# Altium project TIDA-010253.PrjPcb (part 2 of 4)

## Sheet MCU_DockHearder_V3.SchDoc
size A2; Date: Not shown in title block; ApprovedBy: Not shown in title block; CheckedBy: Not shown in title block; Author: Not shown in title block; CompanyName: Not shown in title block; Engineer: Not shown in title block; Organization: Not shown in title block; Address1: Not shown in title block; Address2: Not shown in title block; Address3: Not shown in title block; Address4: Not shown in title block; DocumentNumber: 1; Revision: Use project parameter SCH_Rev; SheetNumber: 6; SheetTotal: 7; PageSetup: Record=PageOptions¦CenterHorizontal=True¦CenterVertical=True¦PrintScale=0.69¦XCorrection=1.00¦YCorrection=1.00¦PrintKind=0¦BorderSize=5000000¦LeftOffset=0¦BottomOffset=0¦Orientation=2¦PaperLength=1000¦PaperWidth=1000¦Scale=100¦PaperSource=15¦PrintQuality=600¦MediaType=1¦DitherType=10¦PaperKind=Letter¦PrintScaleMode=1
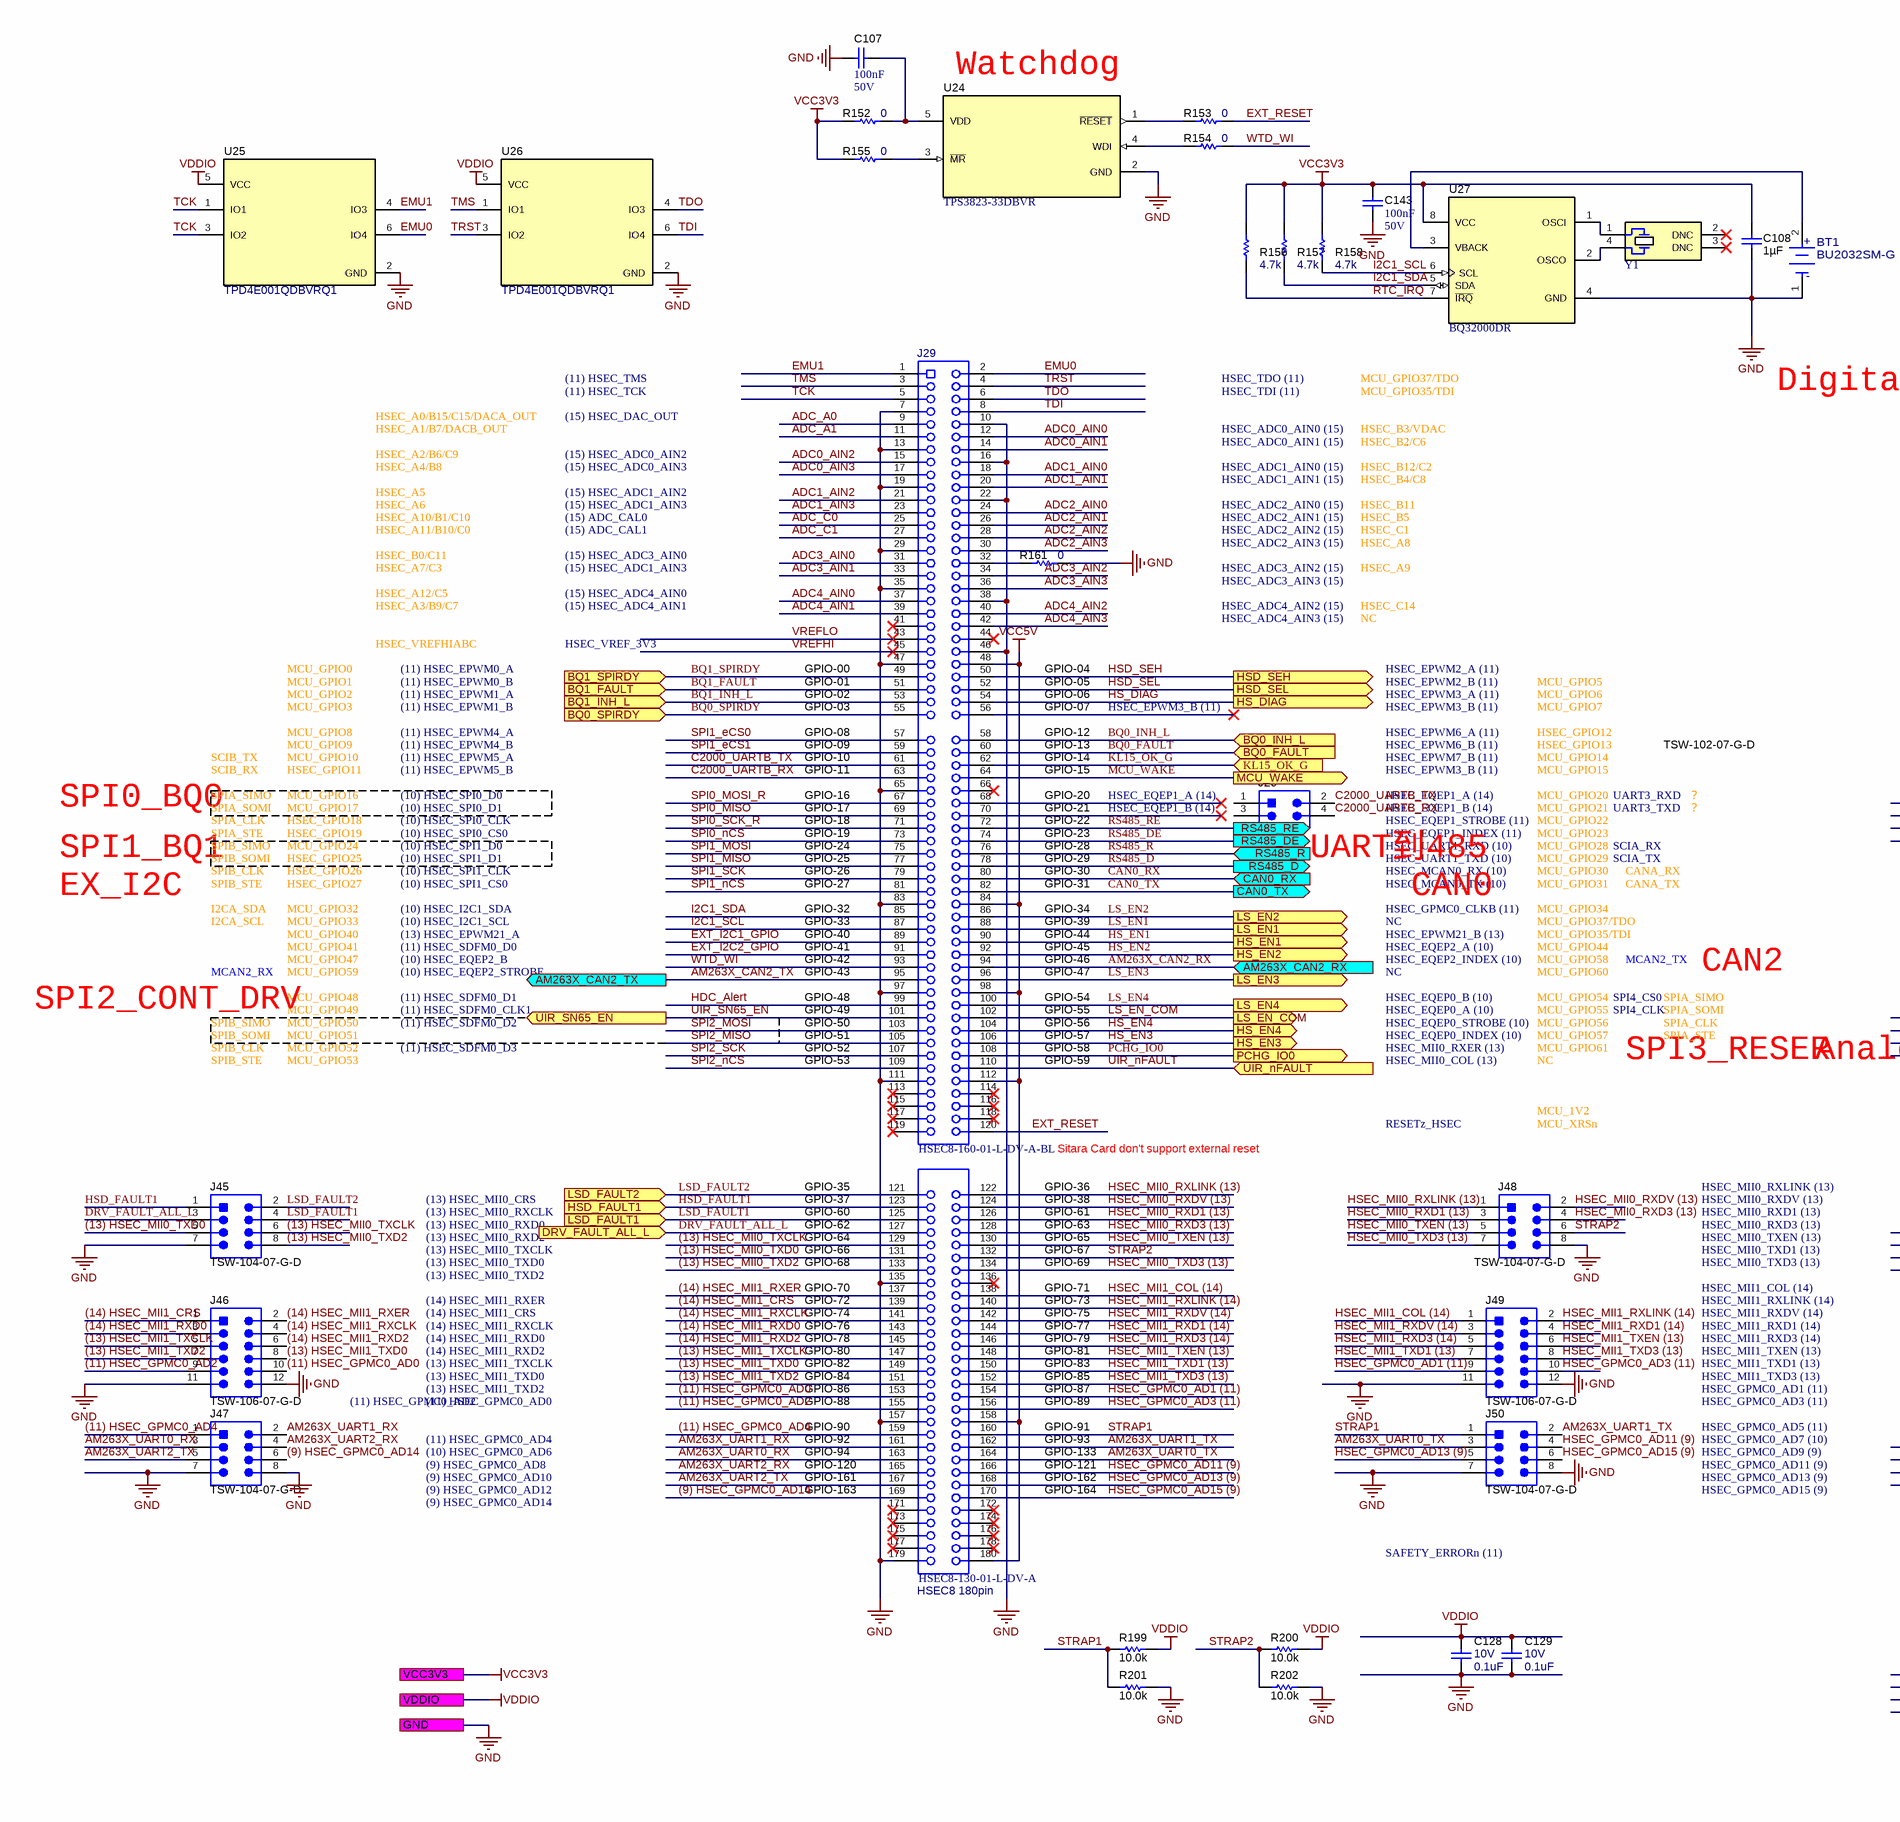
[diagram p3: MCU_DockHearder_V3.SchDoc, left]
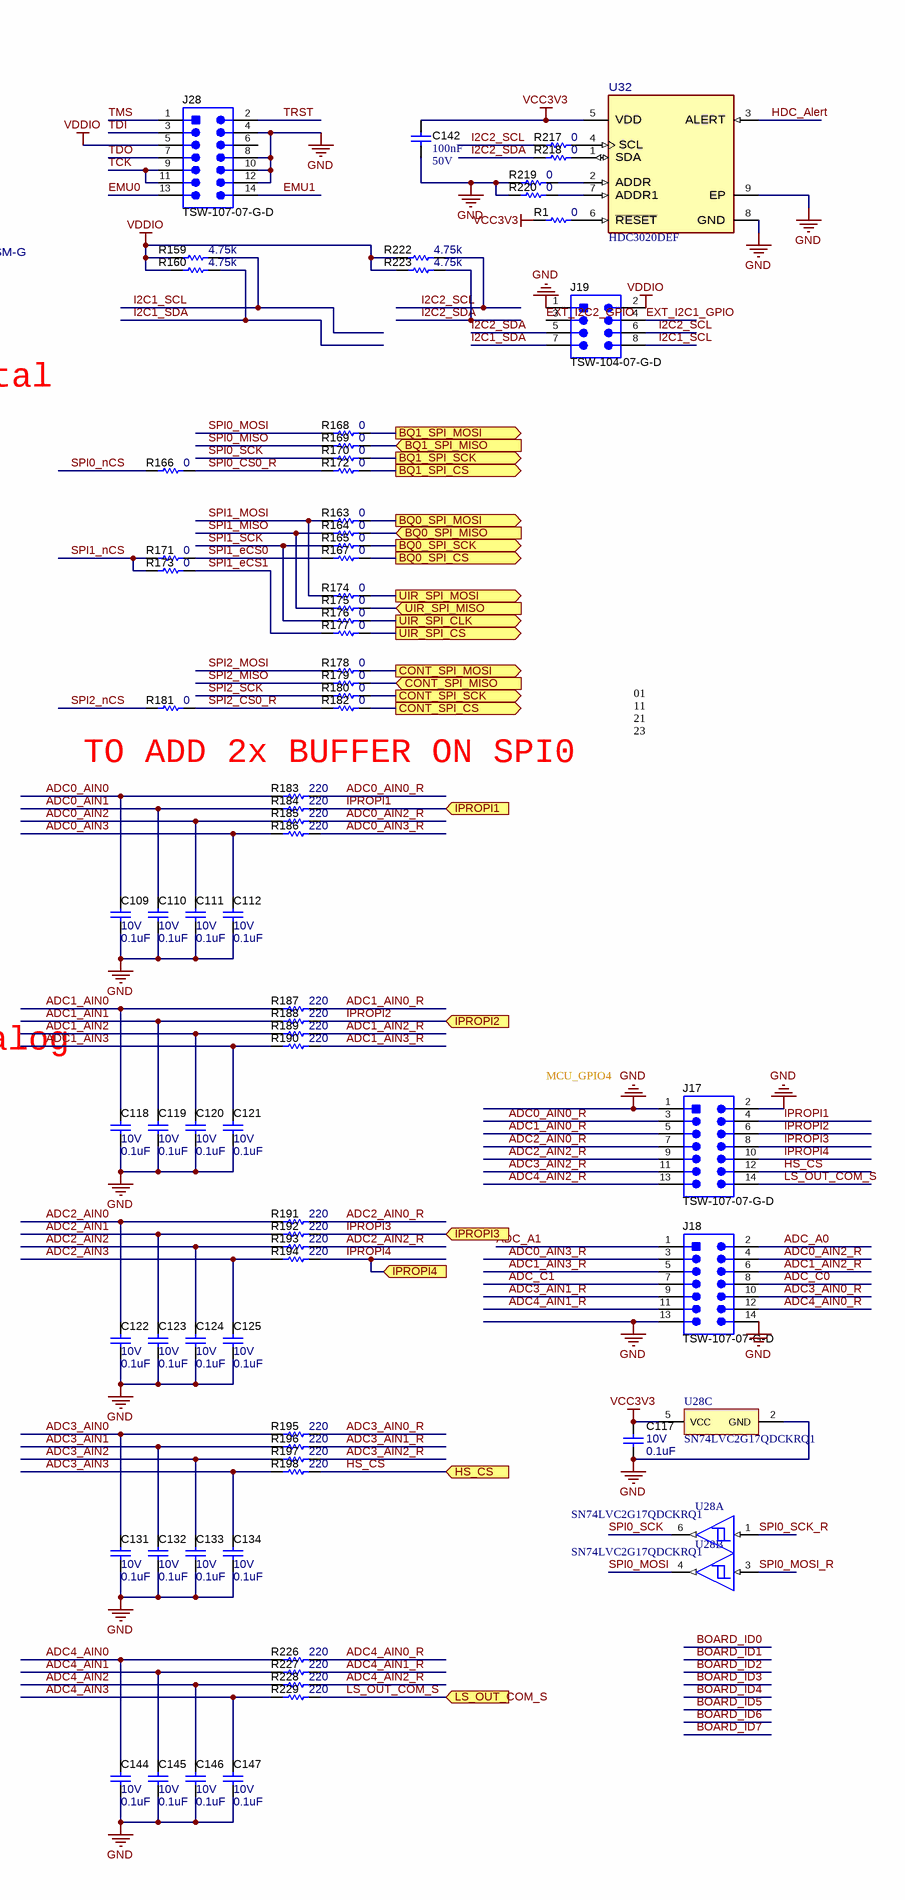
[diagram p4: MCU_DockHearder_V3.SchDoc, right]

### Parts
BT1  BU2032SM-G  [FP-BU2032SM-G_SMT2-MFG]
C107  Cap_F: 100nF  VDC_V: 50V  [0805_HV]  (hidden comment: 08055C104JAT2A)
C108  Cap_F: 1µF  [0603L]  (hidden comment: CGA3E1X7R1E105K080AD)
C109  VDC_V: 10V  ValueDisplayed: 0.1uF  [0402]  (hidden comment: GCM155R71A104KA55D)
C110  VDC_V: 10V  ValueDisplayed: 0.1uF  [0402]  (hidden comment: GCM155R71A104KA55D)
C111  VDC_V: 10V  ValueDisplayed: 0.1uF  [0402]  (hidden comment: GCM155R71A104KA55D)
C112  VDC_V: 10V  ValueDisplayed: 0.1uF  [0402]  (hidden comment: GCM155R71A104KA55D)
C117  VDC_V: 10V  ValueDisplayed: 0.1uF  [0402]  (hidden comment: GCM155R71A104KA55D)
C118  VDC_V: 10V  ValueDisplayed: 0.1uF  [0402]  (hidden comment: GCM155R71A104KA55D)
C119  VDC_V: 10V  ValueDisplayed: 0.1uF  [0402]  (hidden comment: GCM155R71A104KA55D)
C120  VDC_V: 10V  ValueDisplayed: 0.1uF  [0402]  (hidden comment: GCM155R71A104KA55D)
C121  VDC_V: 10V  ValueDisplayed: 0.1uF  [0402]  (hidden comment: GCM155R71A104KA55D)
C122  VDC_V: 10V  ValueDisplayed: 0.1uF  [0402]  (hidden comment: GCM155R71A104KA55D)
C123  VDC_V: 10V  ValueDisplayed: 0.1uF  [0402]  (hidden comment: GCM155R71A104KA55D)
C124  VDC_V: 10V  ValueDisplayed: 0.1uF  [0402]  (hidden comment: GCM155R71A104KA55D)
C125  VDC_V: 10V  ValueDisplayed: 0.1uF  [0402]  (hidden comment: GCM155R71A104KA55D)
C128  VDC_V: 10V  ValueDisplayed: 0.1uF  [0402]  (hidden comment: GCM155R71A104KA55D)
C129  VDC_V: 10V  ValueDisplayed: 0.1uF  [0402]  (hidden comment: GCM155R71A104KA55D)
C131  VDC_V: 10V  ValueDisplayed: 0.1uF  [0402]  (hidden comment: GCM155R71A104KA55D)
C132  VDC_V: 10V  ValueDisplayed: 0.1uF  [0402]  (hidden comment: GCM155R71A104KA55D)
C133  VDC_V: 10V  ValueDisplayed: 0.1uF  [0402]  (hidden comment: GCM155R71A104KA55D)
C134  VDC_V: 10V  ValueDisplayed: 0.1uF  [0402]  (hidden comment: GCM155R71A104KA55D)
C142  Cap_F: 100nF  VDC_V: 50V  [0805_HV]  (hidden comment: 08055C104JAT2A)
C143  Cap_F: 100nF  VDC_V: 50V  [0805_HV]  (hidden comment: 08055C104JAT2A)
C144  VDC_V: 10V  ValueDisplayed: 0.1uF  [0402]  (hidden comment: GCM155R71A104KA55D)
C145  VDC_V: 10V  ValueDisplayed: 0.1uF  [0402]  (hidden comment: GCM155R71A104KA55D)
C146  VDC_V: 10V  ValueDisplayed: 0.1uF  [0402]  (hidden comment: GCM155R71A104KA55D)
C147  VDC_V: 10V  ValueDisplayed: 0.1uF  [0402]  (hidden comment: GCM155R71A104KA55D)
J17  TSW-107-07-G-D  [TSW-107-07-X-D]
J18  TSW-107-07-G-D  [TSW-107-07-X-D]
J19  TSW-104-07-G-D  [TSW-104-07-G-D]
J20  TSW-102-07-G-D  [TSW-102-07-G-D]
J28  TSW-107-07-G-D  [TSW-107-07-X-D]
J29  HSEC8 180pin  [HEADER_HSEC8_180_DV]
J45  TSW-104-07-G-D  [TSW-104-07-G-D]
J46  TSW-106-07-G-D  [TSW-106-07-G-D]
J47  TSW-104-07-G-D  [TSW-104-07-G-D]
J48  TSW-104-07-G-D  [TSW-104-07-G-D]
J49  TSW-106-07-G-D  [TSW-106-07-G-D]
J50  TSW-104-07-G-D  [TSW-104-07-G-D]
R1  ValueDisplayed: 0  [0402]  (hidden comment: RK73Z1ETTP)
R152  ValueDisplayed: 0  [0402]  (hidden comment: CRCW04020000Z0ED)
R153  ValueDisplayed: 0  [0402]  (hidden comment: CRCW04020000Z0ED)
R154  ValueDisplayed: 0  [0402]  (hidden comment: CRCW04020000Z0ED)
R155  ValueDisplayed: 0  [0402]  (hidden comment: CRCW04020000Z0ED)
R156  ValueDisplayed: 4.7k  [0402]  (hidden comment: CRCW04024K70JNED)
R157  ValueDisplayed: 4.7k  [0402]  (hidden comment: CRCW04024K70JNED)
R158  ValueDisplayed: 4.7k  [0402]  (hidden comment: CRCW04024K70JNED)
R159  ValueDisplayed: 4.75k  [0402]  (hidden comment: CRCW04024K75FKED)
R160  ValueDisplayed: 4.75k  [0402]  (hidden comment: CRCW04024K75FKED)
R161  ValueDisplayed: 0  [0402]  (hidden comment: RK73Z1ETTP)
R163  ValueDisplayed: 0  [0402]  (hidden comment: CRCW04020000Z0ED)
R164  ValueDisplayed: 0  [0402]  (hidden comment: CRCW04020000Z0ED)
R165  ValueDisplayed: 0  [0402]  (hidden comment: CRCW04020000Z0ED)
R166  ValueDisplayed: 0  [0402]  (hidden comment: CRCW04020000Z0ED)
R167  ValueDisplayed: 0  [0402]  (hidden comment: CRCW04020000Z0ED)
R168  ValueDisplayed: 0  [0402]  (hidden comment: CRCW04020000Z0ED)
R169  ValueDisplayed: 0  [0402]  (hidden comment: CRCW04020000Z0ED)
R170  ValueDisplayed: 0  [0402]  (hidden comment: CRCW04020000Z0ED)
R171  ValueDisplayed: 0  [0402]  (hidden comment: CRCW04020000Z0ED)
R172  ValueDisplayed: 0  [0402]  (hidden comment: CRCW04020000Z0ED)
R173  ValueDisplayed: 0  [0402]  (hidden comment: CRCW04020000Z0ED)
R174  ValueDisplayed: 0  [0402]  (hidden comment: CRCW04020000Z0ED)
R175  ValueDisplayed: 0  [0402]  (hidden comment: CRCW04020000Z0ED)
R176  ValueDisplayed: 0  [0402]  (hidden comment: CRCW04020000Z0ED)
R177  ValueDisplayed: 0  [0402]  (hidden comment: CRCW04020000Z0ED)
R178  ValueDisplayed: 0  [0402]  (hidden comment: CRCW04020000Z0ED)
R179  ValueDisplayed: 0  [0402]  (hidden comment: CRCW04020000Z0ED)
R180  ValueDisplayed: 0  [0402]  (hidden comment: CRCW04020000Z0ED)
R181  ValueDisplayed: 0  [0402]  (hidden comment: CRCW04020000Z0ED)
R182  ValueDisplayed: 0  [0402]  (hidden comment: CRCW04020000Z0ED)
R183  ValueDisplayed: 220  [0402]  (hidden comment: CRCW0402220RJNED)
R184  ValueDisplayed: 220  [0402]  (hidden comment: CRCW0402220RJNED)
R185  ValueDisplayed: 220  [0402]  (hidden comment: CRCW0402220RJNED)
R186  ValueDisplayed: 220  [0402]  (hidden comment: CRCW0402220RJNED)
R187  ValueDisplayed: 220  [0402]  (hidden comment: CRCW0402220RJNED)
R188  ValueDisplayed: 220  [0402]  (hidden comment: CRCW0402220RJNED)
R189  ValueDisplayed: 220  [0402]  (hidden comment: CRCW0402220RJNED)
R190  ValueDisplayed: 220  [0402]  (hidden comment: CRCW0402220RJNED)
R191  ValueDisplayed: 220  [0402]  (hidden comment: CRCW0402220RJNED)
R192  ValueDisplayed: 220  [0402]  (hidden comment: CRCW0402220RJNED)
R193  ValueDisplayed: 220  [0402]  (hidden comment: CRCW0402220RJNED)
R194  ValueDisplayed: 220  [0402]  (hidden comment: CRCW0402220RJNED)
R195  ValueDisplayed: 220  [0402]  (hidden comment: CRCW0402220RJNED)
R196  ValueDisplayed: 220  [0402]  (hidden comment: CRCW0402220RJNED)
R197  ValueDisplayed: 220  [0402]  (hidden comment: CRCW0402220RJNED)
R198  ValueDisplayed: 220  [0402]  (hidden comment: CRCW0402220RJNED)
R199  ValueDisplayed: 10.0k  [0402]  (hidden comment: RC0402FR-0710KL)
R200  ValueDisplayed: 10.0k  [0402]  (hidden comment: RC0402FR-0710KL)
R201  ValueDisplayed: 10.0k  [0402]  (hidden comment: RC0402FR-0710KL)
R202  ValueDisplayed: 10.0k  [0402]  (hidden comment: RC0402FR-0710KL)
R217  ValueDisplayed: 0  [0402]  (hidden comment: RK73Z1ETTP)
R218  ValueDisplayed: 0  [0402]  (hidden comment: RK73Z1ETTP)
R219  ValueDisplayed: 0  [0402]  (hidden comment: RK73Z1ETTP)
R220  ValueDisplayed: 0  [0402]  (hidden comment: RK73Z1ETTP)
R222  ValueDisplayed: 4.75k  [0402]  (hidden comment: CRCW04024K75FKED)
R223  ValueDisplayed: 4.75k  [0402]  (hidden comment: CRCW04024K75FKED)
R226  ValueDisplayed: 220  [0402]  (hidden comment: CRCW0402220RJNED)
R227  ValueDisplayed: 220  [0402]  (hidden comment: CRCW0402220RJNED)
R228  ValueDisplayed: 220  [0402]  (hidden comment: CRCW0402220RJNED)
R229  ValueDisplayed: 220  [0402]  (hidden comment: CRCW0402220RJNED)
U24  TPS3823-33DBVR  [DBV0005A_N]
U25  TPD4E001QDBVRQ1  [DBV0006A_N]
U26  TPD4E001QDBVRQ1  [DBV0006A_N]
U27  BQ32000DR  [D0008A_L]
U28  SN74LVC2G17QDCKRQ1  [DCK0006A_N]  (parts A,B,C of 3)
U32  HDC3020DEF  [DEF0008A-MFG]
Y1  MC-306 32.7680K-A0:ROHS  [XTAL_MC-306]  (value not drawn)

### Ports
AM263X_CAN2_RX (in), AM263X_CAN2_TX (out), BQ0_FAULT (in), BQ0_INH_L (in), BQ0_SPI_CS (out), BQ0_SPI_MISO (in), BQ0_SPI_MOSI (out), BQ0_SPI_SCK (out), BQ0_SPIRDY (in), BQ1_FAULT (in), BQ1_INH_L (in), BQ1_SPI_CS (out), BQ1_SPI_MISO (in), BQ1_SPI_MOSI (out), BQ1_SPI_SCK (out), BQ1_SPIRDY (in), CAN0_RX (in), CAN0_TX (out), CONT_SPI_CS (out), CONT_SPI_MISO (in), CONT_SPI_MOSI (out), CONT_SPI_SCK (out), DRV_FAULT_ALL_L (in), GND, HS_CS (in), HS_DIAG (out), HS_EN1 (out), HS_EN2 (out), HS_EN3 (out), HS_EN4 (out), HSD_FAULT1 (in), HSD_SEH (out), HSD_SEL (out), IPROPI1 (in), IPROPI2 (in), IPROPI3 (in), IPROPI4 (in), KL15_OK_G (in), LS_EN1 (out), LS_EN2 (out), LS_EN3 (out), LS_EN4 (out), LS_EN_COM (out), LS_OUT_COM_S (in), LSD_FAULT1 (in), LSD_FAULT2 (in), MCU_WAKE (out), PCHG_IO0 (out), RS485_D (out), RS485_DE (out), RS485_R (in), RS485_RE (out), UIR_nFAULT (in), UIR_SN65_EN (out), UIR_SPI_CLK (out), UIR_SPI_CS (out), UIR_SPI_MISO (in), UIR_SPI_MOSI (out), VCC3V3, VDDIO

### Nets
GND: BT1.1(-) C107.2 C108.2 C109.2 C110.2 C111.2 C112.2 C117.2 C118.2 C119.2 C120.2 C121.2 C122.2 C123.2 C124.2 C125.2 C128.2 C129.2 C131.2 C132.2 C133.2 C134.2 C142.1 C143.2 C144.2 C145.2 C146.2 C147.2 J17.1 J17.2 J18.13 J18.14 J19.1 J28.4 J28.8 J28.10 J28.12 J29.7 J29.10 J29.13 J29.16 J29.19 J29.22 J29.29 J29.35 J29.38 J29.46 J29.47 J29.65 J29.83 J29.97 J29.111 J29.135 J29.157 J29.179 J45.7 J46.11 J46.12 J47.7 J47.8 J48.8 J49.11 J49.12 J50.7 J50.8 R161.1 R201.2 R202.2 R219.2 R220.2 U24.2(GND) U25.2(GND) U26.2(GND) U27.4(GND) U28.2(GND) U32.8(GND) U32.9(EP) ; port GND
VCC3V3: C108.1 C117.1 C142.2 C143.1 R1.2 R152.1 R155.1 R156.2 R157.2 R158.2 U27.8(VCC) U28.5(VCC) U32.5(VDD) ; port VCC3V3
VCC5V: J29.48 J29.84 J29.98 J29.112 J29.158 J29.180
VDDIO: C128.1 C129.1 J19.2 J28.5 R159.2 R160.2 R199.2 R200.2 R222.2 R223.2 U25.5(VCC) U26.5(VCC) ; port VDDIO
(9) HSEC_GPMC0_AD14: J29.169 J47.6
(11) HSEC_GPMC0_AD0: J29.153 J46.10
(11) HSEC_GPMC0_AD2: J29.155 J46.9
(11) HSEC_GPMC0_AD4: J29.159 J47.1
(13) HSEC_MII0_TXCLK: J29.129 J45.6
(13) HSEC_MII0_TXD0: J29.131 J45.5
(13) HSEC_MII0_TXD2: J29.133 J45.8
(13) HSEC_MII1_TXCLK: J29.147 J46.5
(13) HSEC_MII1_TXD0: J29.149 J46.8
(13) HSEC_MII1_TXD2: J29.151 J46.7
(14) HSEC_MII1_CRS: J29.139 J46.1
(14) HSEC_MII1_RXCLK: J29.141 J46.4
(14) HSEC_MII1_RXD0: J29.143 J46.3
(14) HSEC_MII1_RXD2: J29.145 J46.6
(14) HSEC_MII1_RXER: J29.137 J46.2
ADC0_AIN0: C109.1 J29.12 R183.1
ADC0_AIN0_R: J17.3 R183.2
ADC0_AIN1: C110.1 J29.14 R184.1
ADC0_AIN2: C111.1 J29.15 R185.1
ADC0_AIN2_R: J18.4 R185.2
ADC0_AIN3: C112.1 J29.17 R186.1
ADC0_AIN3_R: J18.3 R186.2
ADC1_AIN0: C118.1 J29.18 R187.1
ADC1_AIN0_R: J17.5 R187.2
ADC1_AIN1: C119.1 J29.20 R188.1
ADC1_AIN2: C120.1 J29.21 R189.1
ADC1_AIN2_R: J18.6 R189.2
ADC1_AIN3: C121.1 J29.23 R190.1
ADC1_AIN3_R: J18.5 R190.2
ADC2_AIN0: C122.1 J29.24 R191.1
ADC2_AIN0_R: J17.7 R191.2
ADC2_AIN1: C123.1 J29.26 R192.1
ADC2_AIN2: C124.1 J29.28 R193.1
ADC2_AIN2_R: J17.9 R193.2
ADC2_AIN3: C125.1 J29.30 R194.1
ADC3_AIN0: C131.1 J29.31 R195.1
ADC3_AIN0_R: J18.10 R195.2
ADC3_AIN1: C132.1 J29.33 R196.1
ADC3_AIN1_R: J18.9 R196.2
ADC3_AIN2: C133.1 J29.34 R197.1
ADC3_AIN2_R: J17.11 R197.2
ADC3_AIN3: C134.1 J29.36 R198.1
ADC4_AIN0: C144.1 J29.37 R226.1
ADC4_AIN0_R: J18.12 R226.2
ADC4_AIN1: C145.1 J29.39 R227.1
ADC4_AIN1_R: J18.11 R227.2
ADC4_AIN2: C146.1 J29.40 R228.1
ADC4_AIN2_R: J17.13 R228.2
ADC4_AIN3: C147.1 J29.42 R229.1
ADC_A0: J18.2 J29.9
ADC_A1: J18.1 J29.11
ADC_C0: J18.8 J29.25
ADC_C1: J18.7 J29.27
AM263X_CAN2_RX: J29.94 ; port AM263X_CAN2_RX
AM263X_CAN2_TX: J29.95 ; port AM263X_CAN2_TX
AM263X_UART0_RX: J29.163 J47.3
AM263X_UART0_TX: J29.164 J50.3
AM263X_UART1_RX: J29.161 J47.2
AM263X_UART1_TX: J29.162 J50.2
AM263X_UART2_RX: J29.165 J47.4
AM263X_UART2_TX: J29.167 J47.5
BQ0_FAULT: J29.60 ; port BQ0_FAULT
BQ0_INH_L: J29.58 ; port BQ0_INH_L
BQ0_SPI_CS: R167.2 ; port BQ0_SPI_CS
BQ0_SPI_MISO: R164.2 ; port BQ0_SPI_MISO
BQ0_SPI_MOSI: R163.2 ; port BQ0_SPI_MOSI
BQ0_SPI_SCK: R165.2 ; port BQ0_SPI_SCK
BQ0_SPIRDY: J29.55 ; port BQ0_SPIRDY
BQ1_FAULT: J29.51 ; port BQ1_FAULT
BQ1_INH_L: J29.53 ; port BQ1_INH_L
BQ1_SPI_CS: R172.2 ; port BQ1_SPI_CS
BQ1_SPI_MISO: R169.2 ; port BQ1_SPI_MISO
BQ1_SPI_MOSI: R168.2 ; port BQ1_SPI_MOSI
BQ1_SPI_SCK: R170.2 ; port BQ1_SPI_SCK
BQ1_SPIRDY: J29.49 ; port BQ1_SPIRDY
C2000_UARTB_RX: J20.4 J29.63
C2000_UARTB_TX: J20.2 J29.61
CAN0_RX: J29.80 ; port CAN0_RX
CAN0_TX: J29.82 ; port CAN0_TX
CONT_SPI_CS: R182.2 ; port CONT_SPI_CS
CONT_SPI_MISO: R179.2 ; port CONT_SPI_MISO
CONT_SPI_MOSI: R178.2 ; port CONT_SPI_MOSI
CONT_SPI_SCK: R180.2 ; port CONT_SPI_SCK
DRV_FAULT_ALL_L: J29.127 J45.3 ; port DRV_FAULT_ALL_L
EMU0: J28.13 J29.2 U25.6(IO4)
EMU1: J28.14 J29.1 U25.4(IO3)
EXT_I2C1_GPIO: J19.4 J29.89
EXT_I2C2_GPIO: J19.3 J29.91
EXT_RESET: J29.120 R153.2
HDC_Alert: J29.99 U32.3(ALERT)
HS_CS: J17.12 R198.2 ; port HS_CS
HS_DIAG: J29.54 ; port HS_DIAG
HS_EN1: J29.90 ; port HS_EN1
HS_EN2: J29.92 ; port HS_EN2
HS_EN3: J29.106 ; port HS_EN3
HS_EN4: J29.104 ; port HS_EN4
HSD_FAULT1: J29.123 J45.1 ; port HSD_FAULT1
HSD_SEH: J29.50 ; port HSD_SEH
HSD_SEL: J29.52 ; port HSD_SEL
HSEC_GPMC0_AD1 (11): J29.154 J49.9
HSEC_GPMC0_AD3 (11): J29.156 J49.10
HSEC_GPMC0_AD11 (9): J29.166 J50.4
HSEC_GPMC0_AD13 (9): J29.168 J50.5
HSEC_GPMC0_AD15 (9): J29.170 J50.6
HSEC_MII0_RXD1 (13): J29.126 J48.3
HSEC_MII0_RXD3 (13): J29.128 J48.4
HSEC_MII0_RXDV (13): J29.124 J48.2
HSEC_MII0_RXLINK (13): J29.122 J48.1
HSEC_MII0_TXD3 (13): J29.134 J48.7
HSEC_MII0_TXEN (13): J29.130 J48.5
HSEC_MII1_COL (14): J29.138 J49.1
HSEC_MII1_RXD1 (14): J29.144 J49.4
HSEC_MII1_RXD3 (14): J29.146 J49.5
HSEC_MII1_RXDV (14): J29.142 J49.3
HSEC_MII1_RXLINK (14): J29.140 J49.2
HSEC_MII1_TXD1 (13): J29.150 J49.7
HSEC_MII1_TXD3 (13): J29.152 J49.8
HSEC_MII1_TXEN (13): J29.148 J49.6
I2C1_SCL: J19.8 J29.87 R158.1 R159.1 U27.6(SCL)
I2C1_SDA: J19.7 J29.85 R157.1 R160.1 U27.5(SDA)
I2C2_SCL: J19.6 R217.2 R222.1
I2C2_SDA: J19.5 R218.2 R223.1
IPROPI1: J17.4 R184.2 ; port IPROPI1
IPROPI2: J17.6 R188.2 ; port IPROPI2
IPROPI3: J17.8 R192.2 ; port IPROPI3
IPROPI4: J17.10 R194.2 ; port IPROPI4
KL15_OK_G: J29.62 ; port KL15_OK_G
LS_EN1: J29.88 ; port LS_EN1
LS_EN2: J29.86 ; port LS_EN2
LS_EN3: J29.96 ; port LS_EN3
LS_EN4: J29.100 ; port LS_EN4
LS_EN_COM: J29.102 ; port LS_EN_COM
LS_OUT_COM_S: J17.14 R229.2 ; port LS_OUT_COM_S
LSD_FAULT1: J29.125 J45.4 ; port LSD_FAULT1
LSD_FAULT2: J29.121 J45.2 ; port LSD_FAULT2
MCU_WAKE: J29.64 ; port MCU_WAKE
PCHG_IO0: J29.108 ; port PCHG_IO0
RS485_D: J29.78 ; port RS485_D
RS485_DE: J29.74 ; port RS485_DE
RS485_R: J29.76 ; port RS485_R
RS485_RE: J29.72 ; port RS485_RE
RTC_IRQ: R156.1 U27.7(~{IRQ})
SPI0_CS0_R: R166.2 R172.1
SPI0_MISO: J29.69 R169.1
SPI0_MOSI: R168.1 U28.4(2Y)
SPI0_MOSI_R: J29.67 U28.3(2A)
SPI0_nCS: J29.73 R166.1
SPI0_SCK: R170.1 U28.6(1Y)
SPI0_SCK_R: J29.71 U28.1(1A)
SPI1_eCS0: J29.57 R167.1 R171.2
SPI1_eCS1: J29.59 R173.2 R177.1
SPI1_MISO: J29.77 R164.1 R175.1
SPI1_MOSI: J29.75 R163.1 R174.1
SPI1_nCS: J29.81 R171.1 R173.1
SPI1_SCK: J29.79 R165.1 R176.1
SPI2_CS0_R: R181.2 R182.1
SPI2_MISO: J29.105 R179.1
SPI2_MOSI: J29.103 R178.1
SPI2_nCS: J29.109 R181.1
SPI2_SCK: J29.107 R180.1
STRAP1: J29.160 J50.1 R199.1 R201.1
STRAP2: J29.132 J48.6 R200.1 R202.1
TCK: J28.9 J28.11 J29.5 U25.1(IO1) U25.3(IO2)
TDI: J28.3 J29.8 U26.6(IO4)
TDO: J28.7 J29.6 U26.4(IO3)
TMS: J28.1 J29.3 U26.1(IO1)
TRST: J28.2 J29.4 U26.3(IO2)
UIR_nFAULT: J29.110 ; port UIR_nFAULT
UIR_SN65_EN: J29.101 ; port UIR_SN65_EN
UIR_SPI_CLK: R176.2 ; port UIR_SPI_CLK
UIR_SPI_CS: R177.2 ; port UIR_SPI_CS
UIR_SPI_MISO: R175.2 ; port UIR_SPI_MISO
UIR_SPI_MOSI: R174.2 ; port UIR_SPI_MOSI
VREFHI: J29.45
VREFLO: J29.43
WTD_WI: J29.93 R154.2
NetBT1_2: BT1.2(+) U27.3(VBACK)
NetC107_1: C107.1 R152.2 U24.5(VDD)
NetJ29_32: J29.32 R161.2
NetR1_1: R1.1 U32.6(~{RESET})
NetR153_1: R153.1 U24.1(~{RESET})
NetR154_1: R154.1 U24.4(WDI)
NetR155_2: R155.2 U24.3(~{MR})
NetR217_1: R217.1 U32.4(SCL)
NetR218_1: R218.1 U32.1(SDA)
NetR219_1: R219.1 U32.2(ADDR)
NetR220_1: R220.1 U32.7(ADDR1)
NetU27_1: U27.1(OSCI) Y1.1
NetU27_2: U27.2(OSCO) Y1.4

Not connected (* = marked no-connect by the designer): J20 1 3; J28 6; J29 41* 44* 56* 66* 68* 70* 113* 114* 115* 116* 117* 118* 119* 136* 171* 172* 173* 174* 175* 176* 177* 178*; Y1 2(DNC)* 3(DNC)*

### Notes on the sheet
- (near U24) Watchdog
- (11) HSEC_TMS
- (11) HSEC_TCK
- HSEC_TDO (11)
- HSEC_TDI (11)
- MCU_GPIO37/TDO
- MCU_GPIO35/TDI
- Digital
- HSEC_A0/B15/C15/DACA_OUT
- HSEC_A1/B7/DACB_OUT
- HSEC_A2/B6/C9
- HSEC_A4/B8
- (15) HSEC_DAC_OUT
- (15) HSEC_ADC0_AIN2
- (15) HSEC_ADC0_AIN3
- HSEC_ADC0_AIN0 (15)
- HSEC_ADC0_AIN1 (15)
- HSEC_ADC1_AIN0 (15)
- HSEC_B3/VDAC
- HSEC_B2/C6
- HSEC_B12/C2
- HSEC_A5
- HSEC_A6
- HSEC_A10/B1/C10
- HSEC_A11/B10/C0
- (15) ADC_CAL0
- (15) ADC_CAL1
- (15) HSEC_ADC1_AIN2
- (15) HSEC_ADC1_AIN3
- HSEC_ADC1_AIN1 (15)
- HSEC_ADC2_AIN0 (15)
- HSEC_ADC2_AIN1 (15)
- HSEC_ADC2_AIN2 (15)
- HSEC_B4/C8
- HSEC_B11
- HSEC_B5
- HSEC_C1
- HSEC_B0/C11
- HSEC_A7/C3
- HSEC_A12/C5
- (15) HSEC_ADC3_AIN0
- (15) HSEC_ADC4_AIN0
- HSEC_ADC2_AIN3 (15)
- HSEC_ADC3_AIN2 (15)
- HSEC_ADC3_AIN3 (15)
- HSEC_A8
- HSEC_A9
- HSEC_A3/B9/C7
- HSEC_VREFHIABC
- (15) HSEC_ADC4_AIN1
- HSEC_VREF_3V3
- HSEC_ADC4_AIN2 (15)
- HSEC_ADC4_AIN3 (15)
- HSEC_C14
- NC
- MCU_GPIO0
- MCU_GPIO1
- MCU_GPIO2
- MCU_GPIO3
- (11) HSEC_EPWM0_A
- (11) HSEC_EPWM0_B
- (11) HSEC_EPWM1_A
- (11) HSEC_EPWM1_B
- GPIO-00
- GPIO-01
- GPIO-02
- GPIO-03
- GPIO-04
- GPIO-05
- GPIO-06
- GPIO-07
- HSEC_EPWM3_B (11)
- HSEC_EPWM2_A (11)
- HSEC_EPWM2_B (11)
- HSEC_EPWM3_A (11)
- MCU_GPIO5
- MCU_GPIO6
- MCU_GPIO7
- SCIB_TX
- SCIB_RX
- MCU_GPIO8
- MCU_GPIO9
- MCU_GPIO10
- HSEC_GPIO11
- (11) HSEC_EPWM4_A
- (11) HSEC_EPWM4_B
- (11) HSEC_EPWM5_A
- (11) HSEC_EPWM5_B
- GPIO-08
- GPIO-09
- GPIO-10
- GPIO-11
- GPIO-12
- GPIO-13
- GPIO-14
- GPIO-15
- HSEC_EPWM6_A (11)
- HSEC_EPWM6_B (11)
- HSEC_EPWM7_B (11)
- HSEC_GPIO12
- HSEC_GPIO13
- MCU_GPIO14
- MCU_GPIO15
- TO ADD 2x BUFFER ON SPI0
- 01
  11
  21
  23
- SPI0_BQ0
- SPIA_SIMO
- SPIA_SOMI
- SPIA_CLK
- SPIA_STE
- SPIB_SIMO
- MCU_GPIO16
- MCU_GPIO17
- HSEC_GPIO18
- HSEC_GPIO19
- MCU_GPIO24
- (10) HSEC_SPI0_D0
- (10) HSEC_SPI0_D1
- (10) HSEC_SPI0_CLK
- (10) HSEC_SPI0_CS0
- (10) HSEC_SPI1_D0
- GPIO-16
- GPIO-17
- GPIO-18
- GPIO-19
- GPIO-24
- GPIO-20
- GPIO-21
- GPIO-22
- GPIO-23
- GPIO-28
- HSEC_EQEP1_A (14)
- HSEC_EQEP1_B (14)
- HSEC_EQEP1_STROBE (11)
- HSEC_EQEP1_INDEX (11)
- HSEC_UART1_RXD (10)
- MCU_GPIO20
- MCU_GPIO21
- MCU_GPIO22
- MCU_GPIO23
- MCU_GPIO28
- UART3_RXD
- UART3_TXD
- SCIA_RX
- ？
- SPI1_BQ1
- EX_I2C
- I2CA_SDA
- SPIB_SOMI
- SPIB_CLK
- SPIB_STE
- HSEC_GPIO25
- HSEC_GPIO26
- HSEC_GPIO27
- MCU_GPIO32
- (10) HSEC_SPI1_D1
- (10) HSEC_SPI1_CLK
- (10) HSEC_SPI1_CS0
- (10) HSEC_I2C1_SDA
- GPIO-25
- GPIO-26
- GPIO-27
- GPIO-32
- GPIO-29
- GPIO-30
- GPIO-31
- GPIO-34
- (near J20) UART到485
- HSEC_UART1_TXD (10)
- HSEC_MCAN0_RX (10)
- HSEC_MCAN0_TX (10)
- HSEC_GPMC0_CLKB (11)
- CAN0
- MCU_GPIO29
- MCU_GPIO30
- MCU_GPIO31
- MCU_GPIO34
- SCIA_TX
- CANA_RX
- CANA_TX
- MCAN2_RX
- I2CA_SCL
- MCU_GPIO33
- MCU_GPIO40
- MCU_GPIO41
- MCU_GPIO47
- MCU_GPIO59
- (10) HSEC_I2C1_SCL
- (13) HSEC_EPWM21_A
- (11) HSEC_SDFM0_D0
- (10) HSEC_EQEP2_B
- (10) HSEC_EQEP2_STROBE
- GPIO-33
- GPIO-40
- GPIO-41
- GPIO-42
- GPIO-43
- GPIO-39
- GPIO-46
- GPIO-47
- GPIO-44
- GPIO-45
- HSEC_EPWM21_B (13)
- HSEC_EQEP2_A (10)
- HSEC_EQEP2_INDEX (10)
- MCU_GPIO44
- MCU_GPIO58
- MCU_GPIO60
- MCAN2_TX
- CAN2
- SPI2_CONT_DRV
- MCU_GPIO48
- MCU_GPIO49
- MCU_GPIO50
- MCU_GPIO51
- (11) HSEC_SDFM0_D1
- (11) HSEC_SDFM0_CLK1
- (11) HSEC_SDFM0_D2
- GPIO-48
- GPIO-49
- GPIO-50
- GPIO-51
- GPIO-54
- GPIO-55
- GPIO-56
- GPIO-57
- HSEC_EQEP0_B (10)
- HSEC_EQEP0_STROBE (10)
- HSEC_EQEP0_INDEX (10)
- HSEC_EQEP0_A (10)
- MCU_GPIO54
- MCU_GPIO55
- MCU_GPIO56
- MCU_GPIO57
- SPI4_CS0
- SPI4_CLK
- MCU_GPIO52
- MCU_GPIO53
- (11) HSEC_SDFM0_D3
- GPIO-52
- GPIO-53
- GPIO-58
- GPIO-59
- HSEC_MII0_RXER (13)
- HSEC_MII0_COL (13)
- MCU_GPIO61
- SPI3_RESER
- Analog
- MCU_GPIO4
- Sitara Card don't support external reset
- RESETz_HSEC
- MCU_1V2
- MCU_XRSn
- (13) HSEC_MII0_CRS
- (13) HSEC_MII0_RXCLK
- (13) HSEC_MII0_RXD0
- GPIO-35
- GPIO-37
- GPIO-60
- GPIO-62
- GPIO-36
- GPIO-38
- GPIO-61
- GPIO-63
- HSEC_MII0_RXLINK (13)
- HSEC_MII0_RXD1 (13)
- HSEC_MII0_RXD3 (13)
- HSEC_MII0_RXDV (13)
- (13) HSEC_MII0_RXD2
- (13) HSEC_MII0_TXCLK
- (13) HSEC_MII0_TXD0
- (13) HSEC_MII0_TXD2
- GPIO-64
- GPIO-66
- GPIO-68
- GPIO-70
- GPIO-65
- GPIO-67
- GPIO-69
- GPIO-71
- HSEC_MII0_TXEN (13)
- HSEC_MII0_TXD1 (13)
- HSEC_MII0_TXD3 (13)
- HSEC_MII1_COL (14)
- (14) HSEC_MII1_RXER
- (14) HSEC_MII1_CRS
- (14) HSEC_MII1_RXCLK
- (14) HSEC_MII1_RXD0
- (14) HSEC_MII1_RXD2
- GPIO-72
- GPIO-74
- GPIO-76
- GPIO-78
- GPIO-80
- GPIO-73
- GPIO-75
- GPIO-77
- GPIO-79
- GPIO-81
- HSEC_MII1_RXDV (14)
- HSEC_MII1_RXD1 (14)
- HSEC_MII1_RXD3 (14)
- HSEC_MII1_RXLINK (14)
- HSEC_MII1_TXEN (13)
- (11) HSEC_GPMC0_AD2
- (13) HSEC_MII1_TXCLK
- (13) HSEC_MII1_TXD0
- (13) HSEC_MII1_TXD2
- (11) HSEC_GPMC0_AD0
- GPIO-82
- GPIO-84
- GPIO-86
- GPIO-88
- GPIO-83
- GPIO-85
- GPIO-87
- GPIO-89
- HSEC_MII1_TXD1 (13)
- HSEC_MII1_TXD3 (13)
- HSEC_GPMC0_AD1 (11)
- HSEC_GPMC0_AD3 (11)
- (11) HSEC_GPMC0_AD4
- (10) HSEC_GPMC0_AD6
- (9) HSEC_GPMC0_AD8
- (9) HSEC_GPMC0_AD10
- GPIO-90
- GPIO-92
- GPIO-94
- GPIO-120
- GPIO-161
- GPIO-91
- GPIO-93
- GPIO-121
- GPIO-133
- GPIO-162
- HSEC_GPMC0_AD5 (11)
- HSEC_GPMC0_AD7 (10)
- HSEC_GPMC0_AD9 (9)
- HSEC_GPMC0_AD11 (9)
- HSEC_GPMC0_AD13 (9)
- (9) HSEC_GPMC0_AD12
- (9) HSEC_GPMC0_AD14
- GPIO-163
- GPIO-164
- HSEC_GPMC0_AD15 (9)
- SAFETY_ERRORn (11)

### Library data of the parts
BT1 = CMP-0032780-1: Battery Holder Coin 20MM SMD; Manufacturer: MPD; AEC Qualified: No; Conn Orientation: Vertical; ContactFinish: Gold,Nickel; SizeZ_mm: 5.7mm
C107 C142 C143 = CMP-0007631-2: CAP, CERM, 0.1 uF, 50 V, +/- 5%, X7R, 0805; Manufacturer: AVX; TaMin_C: -55°C; ESR_ohm: 0.024; Polarized: N; SizeAreaWB_mm2: 6.75; Value1: 0.024 ohm; U/M: EA; Value: 0.1uF; TaMax_C: 125°C; SizeZ_mm: 1.45; SizeX_mm: 2; SizeY_mm: 1.25; Cap_Case: 0805; SizeArea_mm2: 2.5; AEC Category: Q200
C108 = CMP-0082523-1: CAP, CERM, 1 µF, 25 V,+/- 10%, X7R, AEC-Q200 Grade 1, 0603; Manufacturer: TDK; SizeAreaWB_mm2: 4.68; SizeArea_mm2: 1.28; AEC Qualified: Y; AEC Category: Q200; Value: 1uF; TaMax_C: 125°C; SizeZ_mm: 1; Polarized: N; TaMin_C: -55°C; VDC_V: 25V; SizeY_mm: 0.8; U/M: EA; SizeX_mm: 1.6; Cap_Case: 0603
C109-C112 C117-C125 C128 C129 C131-C134 C144-C147 = CMP-0006350-2: CAP, CERM, 0.1 uF, 10 V, +/- 10%, X7R, AEC-Q200 Grade 1, 0402; Manufacturer: MuRata; TaMin_C: -55°C; Polarized: N; SizeAreaWB_mm2: 3; Value1: Unknown; U/M: EA; Value: 0.1uF; TaMax_C: 125°C; SizeZ_mm: 0.6; SizeX_mm: 1; SizeY_mm: 0.5; AEC Qualified: Y; Cap_F: 100nF; AEC Category: Q200
J17 J18 J28 = CMP-0075415-2: Header, 100mil, 7x2, Gold, TH; Manufacturer: Samtec; Pitch_mm: 2.54; Cert_VDE: N; Gender: Male; Cert_CSA: Y; Voltage_V: 550V; Green_REACh: Passed; Current_A: 6.3A; Green_Lifecycle: Active; Row_Count: 2
J19 J45 J47 J48 J50 = CMP-0075408-3: Header, 100mil, 4x2, Gold, TH; Manufacturer: Samtec; Gender: Male; Row_Count: 2; Cert_CSA: Y; Pitch_mm: 2.54; Green_REACh: Passed; Voltage_V: 550V; Current_A: 6.3A; Green_Lifecycle: Active; Cert_CULUS: N
J20 = CMP-0075404-1: Header, 100mil, 2x2, Gold, TH; Manufacturer: Samtec; Pitch_mm: 2.54; Cert_VDE: N; Gender: Male; Cert_CSA: Y; Voltage_V: 550V; Green_REACh: Passed; Current_A: 6.3A; CT: False; Green_Lifecycle: Active; Row_Count: 2; CNHeader: True
J29 = HEADER_HSEC8180_EDGE_F2837X: 180 pin (120 + 60) HSEC8 socket, samtec; MANF PART NUMBER: HSEC8-130-01-L-DV-A & HSEC8-160-01-L-DV-A-BL
J46 J49 = CMP-0075412-2: Header, 100mil, 6x2, Gold, TH; Manufacturer: Samtec; Pitch_mm: 2.54; Cert_VDE: N; Gender: Male; Cert_CSA: Y; Voltage_V: 550V; Green_REACh: Passed; Current_A: 6.3A; Green_Lifecycle: Active; Row_Count: 2
R1 R161 R217-R220 = CMP-0027007-2: RES, 0, 5%, 0.063 W, AEC-Q200 Grade 0, 0402; Manufacturer: KOA Speer; Power_W: 63mW; TempCo: ppm/C; Value_Code: 0000; U/M: EA; Value: 0; EIA_Code: E24; SizeX_mm: 1; SizeY_mm: 0.5; SizeZ_mm: 0.6; Value2: 0.063W; AEC Qualified: Y; AEC Category: Q200
R152-R155 R163-R182 = CMP-0026822-3: RES, 0, 5%, 0.063 W, AEC-Q200 Grade 0, 0402; Manufacturer: Vishay-Dale; Power_W: 63mW; TempCo: 200 ppm/C; Value_Code: 0000; Value: 0; EIA_Code: E24; SizeX_mm: 1; SizeY_mm: 0.5; SizeZ_mm: 0.6; Value2: 0.063W; AEC Qualified: Y; VDC_V: 50V; AEC Category: Q200
R156-R158 = CMP-0026938-5: RES, 4.7 k, 5%, 0.063 W, AEC-Q200 Grade 0, 0402; Manufacturer: Vishay-Dale; Power_W: 63mW; TempCo: 200 ppm/C; Value_Code: 4k70; Value: 4.7k; EIA_Code: E24; SizeX_mm: 1; SizeY_mm: 0.5; SizeZ_mm: 0.6; Value2: 0.063W; AEC Qualified: Y; VDC_V: 50V; AEC Category: Q200; AEC Grade: 0
R159 R160 R222 R223 = CMP-0026412-2: RES, 4.75 k, 1%, 0.063 W, AEC-Q200 Grade 0, 0402; Manufacturer: Vishay-Dale; Power_W: 63mW; TempCo: 100 ppm/C; Value_Code: 4k75; Value: 4.75k; EIA_Code: E96; SizeX_mm: 1; SizeY_mm: 0.5; SizeZ_mm: 0.6; Value2: 0.063W; AEC Qualified: Y; VDC_V: 50V; AEC Category: Q200; AEC Grade: 0
R183-R198 R226-R229 = CMP-0026878-3: RES, 220, 5%, 0.063 W, AEC-Q200 Grade 0, 0402; Manufacturer: Vishay-Dale; Power_W: 63mW; TempCo: 200 ppm/C; Value_Code: 220R; Value: 220; EIA_Code: E24; SizeX_mm: 1; SizeY_mm: 0.5; SizeZ_mm: 0.6; Value2: 0.063W; AEC Qualified: Y; VDC_V: 50V; AEC Category: Q200; AEC Grade: 0
R199-R202 = CMP-0078669-1: RES, 10.0 k, 1%, 0.063 W, 0402; Manufacturer: Yageo America; Power_W: 63mW; Green_Lifecycle: Active; TempCo: 100 ppm/C; Value_Code: 10k0; Green_REACh: Passed; Value: 10.0k; EIA_Code: E96; Res_ohm: 10k; SizeX_mm: 1; SizeY_mm: 0.5; SizeZ_mm: 0.6; Value2: 0.063W; AEC Qualified: N; AEC Category: Q200
U24 = CMP-0860515-1: Voltage supervisor (reset IC) with watchdog and manual reset, DBV0005A (SOT-23-5); Alternate PartNumber: TPS3823-33DBVT; Alternate Manufacturer: Texas Instruments; AEC Category: Q200; SizeZ_mm: 1.45; SizeY_mm: 2.9; SizeArea_mm2: 8.12; Rating: Catalog; SizeAreaWB_mm2: 14.82; AEC Qualified: N; SizeX_mm: 2.8
U25 U26 = CMP-0066599-1: Automotive Low-Capacitance 4-Channel +/-15-kV ESD Protection Array for High-Speed Data Interfaces, DBV0006A (SOT-23-6); Alternate Manufacturer: Texas Instruments; SizeAreaWB_mm2: 14.82; U/M: EA; SizeZ_mm: 1.45; SizeX_mm: 2.8; SizeY_mm: 2.9; SizeArea_mm2: 8.12; CompType: IC
U27 = CMP-0075887-1: Serial RTC with Battery Backup and Trickle Charge, D0008A (SOIC-8); Manufacturer: Texas Instruments; SizeAreaWB_mm2: 56.58; SizeArea_mm2: 30.38; SizeZ_mm: 1.75; SizeY_mm: 6.2; U/M: EA; CompType: IC; SizeX_mm: 4.9
U28 = CMP-0051906-3: Automotive Catalog Dual Schmitt-Trigger Buffer, DCK0006A (SOT-SC70-6); Manufacturer: Texas Instruments; Generic Part Number: SN74LVC2G17-Q1; Output Type: CMOS; Bits(#): 2; Input Type: CMOS/TTL; Technology Family: LVC; Schmitt Trigger: Yes; 3-State Output: No; VCC(Max)(V): 5.5; Output Drive (IOL/IOH)(Max)(mA): 32/-32; ICC @ Nom Voltage(Max)(mA): 0.01; VCC(Min)(V): 1.65; F @ Nom Voltage(Max)(Mhz): 150; Logic: True; Voltage(Nom)(V): 1.8,2.5,3.3,5; tpd @ Nom Voltage(Max)(ns): 9.3,5.7,5.4,4.3; AEC Category: Q200; AEC Qualified: Y; CompType: IC; SizeAreaWB_mm2: 9.3; SizeArea_mm2: 4.2; SizeX_mm: 2.1; SizeY_mm: 2.0; SizeZ_mm: 1.1
U32 = CMP-0087942-2: Integrated Humidity and Temperature Digital Sensor; Manufacturer: Texas Instruments; AEC Category: Q200; AEC Qualified: No; SizeZ_mm: 0.8mm; CompType: IC
Y1 = CMP-0004577-3: Crystal, 32.768 kHz, 12.5pF, SMD; Manufacturer: Epson; TaMin_C: -40°C; Frequency Stability: +/-20ppm; TaMax_C: 85°C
